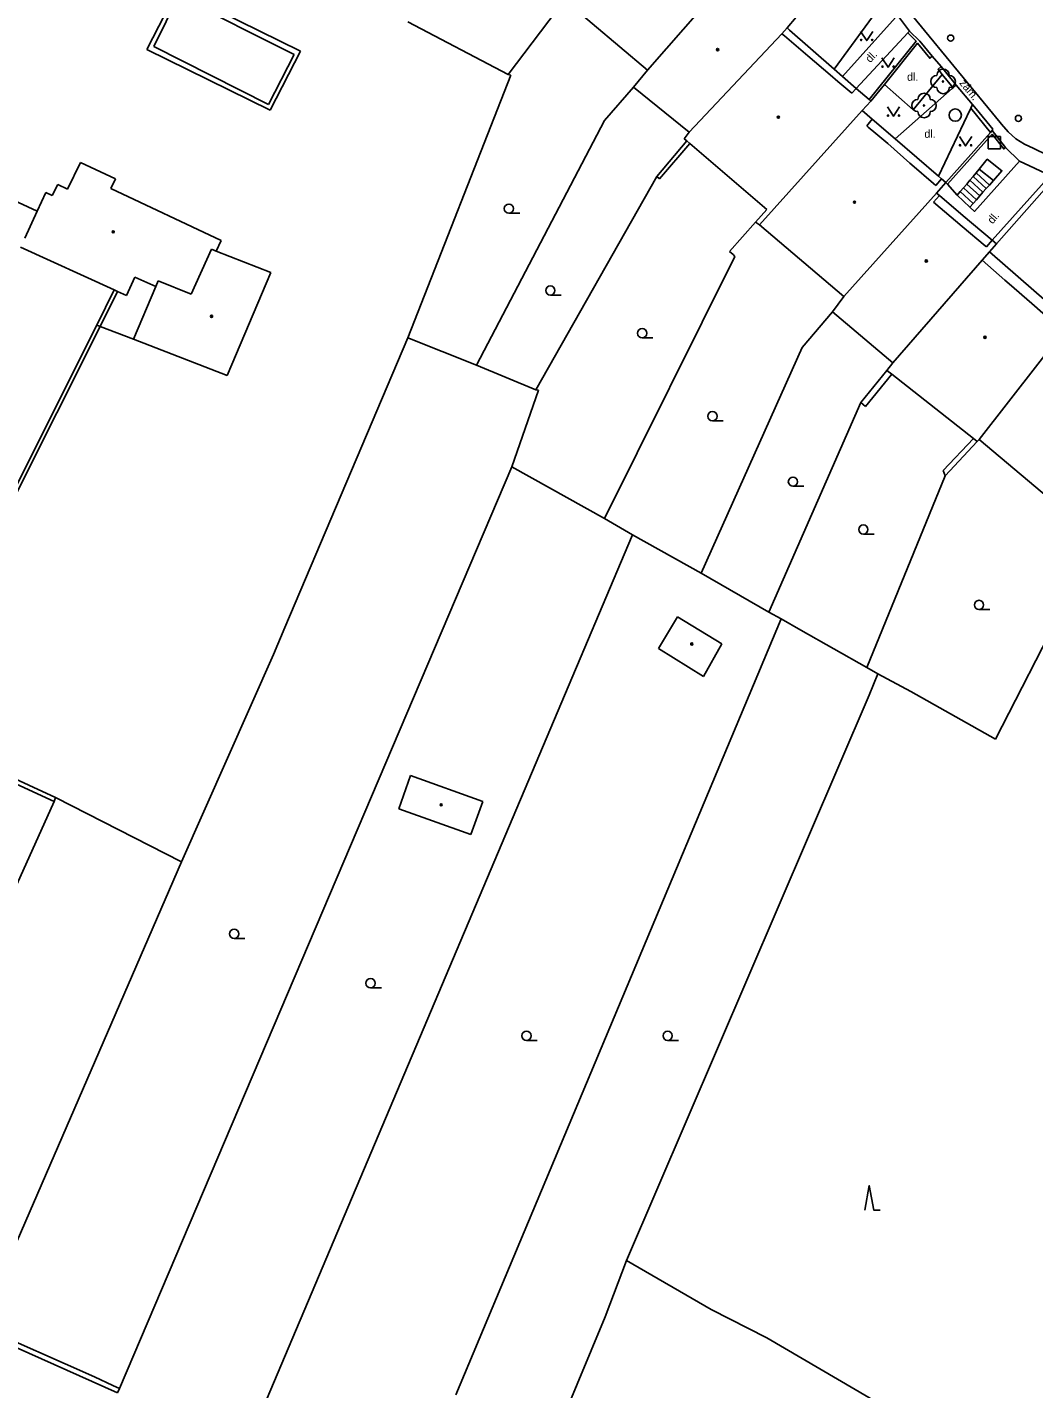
# Model space of a CAD drawing. Extents: x -600309 to -598967, y -1161267 to -1160292.
# Drawn here: x -600023.6 to -599941.8, y -1160821.7 to -1160711.1 of the extents above; entities that cross this region are included whole.
import ezdxf

# ---------------------------------------------------------------- set-up
doc = ezdxf.new("R2010")
doc.units = 0
for name, color, linetype in [('Level 10', 7, 'Continuous'), ('Level 11', 7, 'Continuous'), ('Level 22', 7, 'Continuous'), ('Level 26', 7, 'Continuous'), ('Level 27', 7, 'Continuous'), ('Level 28', 7, 'Continuous'), ('Level 36', 7, 'Continuous'), ('Level 39', 7, 'Continuous'), ('Level 40', 7, 'Continuous'), ('Level 5', 7, 'Continuous'), ('Level 51', 7, 'Continuous'), ('Level 52', 7, 'Continuous'), ('Level 54', 7, 'Continuous'), ('Level 8', 7, 'Continuous')]:
    doc.layers.add(name, color=color, linetype=linetype)

msp = doc.modelspace()

# ---------------------------------------------------------------- linework, layer by layer
at = {"layer": 'Level 10'}
for points in [[(-599972.15, -1160685.37), (-599963.56, -1160695.65), (-599958.13, -1160702.29), (-599951.34, -1160710.61), (-599944.5652, -1160718.8302), (-599944.45, -1160718.9699)], [(-599944.45, -1160718.9699), (-599943.9099, -1160719.6), (-599943.29, -1160720.15), (-599942.59, -1160720.6), (-599941.84, -1160720.95)], [(-599941.84, -1160720.95), (-599921.83, -1160730.68), (-599912.84, -1160735.04), (-599897.82, -1160742.4699), (-599882.1599, -1160750.1), (-599876.92, -1160738.9699), (-599874.96, -1160734.65), (-599883.28, -1160730.96), (-599891.87, -1160727.45), (-599900.5, -1160724)]]:
    msp.add_lwpolyline(points, dxfattribs=at)
at = {"layer": 'Level 11'}
for points in [[(-599958.05, -1160714.51), (-599954.12, -1160709.13)], [(-599953.07, -1160710.29), (-599957.38, -1160715.09)], [(-599952.9, -1160710.1), (-599951.92, -1160711.4099)], [(-599956.25, -1160716.08), (-599952.06, -1160711.56)], [(-599952.06, -1160711.56), (-599951.39, -1160712.2199), (-599955.21, -1160716.9699)], [(-599952.06, -1160711.56), (-599951.92, -1160711.4099)], [(-599951.92, -1160711.4099), (-599951.09, -1160712.23), (-599950.1, -1160713.45)], [(-599950.1, -1160713.45), (-599950.29, -1160713.61), (-599951.27, -1160712.4), (-599953.96, -1160715.75)], [(-599950.1, -1160713.45), (-599949.35, -1160714.29)], [(-599953.96, -1160715.75), (-599951.63, -1160717.79), (-599949.27, -1160714.93)], [(-599949.27, -1160714.93), (-599949.61, -1160714.5), (-599949.35, -1160714.29)], [(-599949.35, -1160714.29), (-599948.33, -1160715.55), (-599948.14, -1160715.79)], [(-599949.27, -1160714.93), (-599948.39, -1160716.01)], [(-599953.96, -1160715.75), (-599955.06, -1160717.1)], [(-599948.39, -1160716.01), (-599948.45, -1160716.06), (-599953.1, -1160720.1599)], [(-599948.14, -1160715.79), (-599948.39, -1160716.01)], [(-599948.14, -1160715.79), (-599946.81, -1160717.37)], [(-599949.57, -1160723.2), (-599947, -1160717.77), (-599946.95, -1160717.67)], [(-599946.95, -1160717.67), (-599946.81, -1160717.37)], [(-599946.95, -1160717.67), (-599945.34, -1160719.64)], [(-599946.81, -1160717.37), (-599946.52, -1160717.7199), (-599945.17, -1160719.37), (-599945.2, -1160719.48)], [(-599945.2, -1160719.48), (-599945.34, -1160719.64)], [(-599945.2, -1160719.48), (-599944.12, -1160720.85)], [(-599945.34, -1160719.64), (-599948.98, -1160723.71)], [(-599945.21, -1160719.79), (-599948.83, -1160723.84)], [(-599945.21, -1160719.79), (-599944.27, -1160720.98), (-599944.12, -1160720.85)], [(-599944.12, -1160720.85), (-599943, -1160721.9699)], [(-599947.02, -1160725.7), (-599946.64, -1160726.05), (-599943, -1160721.9699)], [(-599946.5, -1160722.9099), (-599946.26, -1160722.63)], [(-599946.26, -1160722.63), (-599945.61, -1160721.81), (-599944.42, -1160722.75), (-599945.11, -1160723.55)], [(-599945.11, -1160723.55), (-599946.26, -1160722.63)], [(-599943, -1160721.9699), (-599940.51, -1160723.14)], [(-599948.98, -1160723.71), (-599948.83, -1160723.84)], [(-599948.83, -1160723.84), (-599948.06, -1160724.74)], [(-599947.54, -1160724.13), (-599947.28, -1160723.83)], [(-599947.28, -1160723.83), (-599947.02, -1160723.52)], [(-599947.28, -1160723.83), (-599946.2199, -1160724.8)], [(-599947.02, -1160723.52), (-599946.76, -1160723.2199)], [(-599947.02, -1160723.52), (-599945.96, -1160724.5)], [(-599946.76, -1160723.2199), (-599946.5, -1160722.9099)], [(-599946.76, -1160723.2199), (-599945.69, -1160724.2)], [(-599946.5, -1160722.9099), (-599945.43, -1160723.9099)], [(-599945.43, -1160723.9099), (-599945.69, -1160724.2)], [(-599945.11, -1160723.55), (-599945.43, -1160723.9099)], [(-599945.2, -1160728.39), (-599940.51, -1160723.14)], [(-599940.14, -1160723.35), (-599944.87, -1160728.7)], [(-599948.06, -1160724.74), (-599947.8, -1160724.44)], [(-599948.06, -1160724.74), (-599947.02, -1160725.7)], [(-599947.8, -1160724.44), (-599947.54, -1160724.13)], [(-599947.8, -1160724.44), (-599946.76, -1160725.4)], [(-599947.54, -1160724.13), (-599946.49, -1160725.1)], [(-599946.2199, -1160724.8), (-599946.49, -1160725.1)], [(-599945.96, -1160724.5), (-599946.2199, -1160724.8)], [(-599945.69, -1160724.2), (-599945.96, -1160724.5)], [(-599946.76, -1160725.4), (-599947.02, -1160725.7)], [(-599946.49, -1160725.1), (-599946.76, -1160725.4)], [(-600016.13, -1160821.67), (-600016.29, -1160822.03)]]:
    msp.add_lwpolyline(points, dxfattribs=at)
at = {"layer": 'Level 22'}
for centre in [(-599949.2, -1160715.5), (-599950.75, -1160717.45)]:
    msp.add_circle(centre, 0.05, dxfattribs=at)
for centre, start, end in [((-599949.7, -1160715.5), 90, 270), ((-599949.2, -1160715), 0, 180), ((-599948.7, -1160715.5), 270, 90), ((-599949.2, -1160716), 180, 0), ((-599951.25, -1160717.45), 90, 270), ((-599950.75, -1160716.95), 0, 180), ((-599950.25, -1160717.45), 270, 90), ((-599950.75, -1160717.95), 180, 0)]:
    msp.add_arc(centre, 0.5, start, end, dxfattribs=at)
at = {"layer": 'Level 26'}
msp.add_lwpolyline([(-599945.54, -1160720.9699), (-599944.54, -1160720.9699), (-599944.54, -1160719.9699), (-599945.54, -1160719.9699)], close=True, dxfattribs=at)
at = {"layer": 'Level 27'}
msp.add_circle((-599948.21, -1160718.23), 0.5, dxfattribs=at)
at = {"layer": 'Level 28'}
for centre in [(-599948.58, -1160711.98), (-599943.08, -1160718.5)]:
    msp.add_circle(centre, 0.25, dxfattribs=at)
at = {"layer": 'Level 36'}
for p, q in [((-599984.48, -1160726.205), (-599983.605, -1160726.205)), ((-599981.11, -1160732.855), (-599980.235, -1160732.855)), ((-599973.65, -1160736.325), (-599972.775, -1160736.325)), ((-599967.94, -1160743.065), (-599967.065, -1160743.065)), ((-599961.4, -1160748.385), (-599960.525, -1160748.385)), ((-599955.68, -1160752.265), (-599954.805, -1160752.265)), ((-599946.28, -1160758.395), (-599945.405, -1160758.395)), ((-600006.8, -1160785.115), (-600005.925, -1160785.115)), ((-599995.7199, -1160789.125), (-599994.8449, -1160789.125)), ((-599983.05, -1160793.395), (-599982.175, -1160793.395)), ((-599971.58, -1160793.395), (-599970.705, -1160793.395))]:
    msp.add_line(p, q, dxfattribs=at)
for points in [[(-599955.9099, -1160711.43), (-599955.4099, -1160712.18), (-599954.9099, -1160711.43)], [(-599954.17, -1160713.59), (-599953.67, -1160714.34), (-599953.17, -1160713.59)], [(-599953.73, -1160717.57), (-599953.23, -1160718.32), (-599952.73, -1160717.57)], [(-599947.87, -1160719.98), (-599947.37, -1160720.73), (-599946.87, -1160719.98)], [(-599955.569, -1160807.1879), (-599955.194, -1160805.1879), (-599954.819, -1160807.1879), (-599954.319, -1160807.1879)]]:
    msp.add_lwpolyline(points, dxfattribs=at)
for centre, radius in [((-599955.8601, -1160712.1298), 0.05), ((-599954.9607, -1160712.1298), 0.05), ((-599954.1202, -1160714.2898), 0.05), ((-599953.2208, -1160714.2898), 0.05), ((-599953.6802, -1160718.2698), 0.05), ((-599952.7808, -1160718.2698), 0.05), ((-599947.8202, -1160720.6798), 0.05), ((-599946.9208, -1160720.6798), 0.05), ((-599984.4801, -1160725.8299), 0.375), ((-599981.1101, -1160732.4799), 0.375), ((-599973.6501, -1160735.9499), 0.375), ((-599967.9401, -1160742.6899), 0.375), ((-599961.4001, -1160748.0099), 0.375), ((-599955.6801, -1160751.8899), 0.375), ((-599946.2801, -1160758.0199), 0.375), ((-600006.8001, -1160784.7399), 0.375), ((-599995.72, -1160788.7499), 0.375), ((-599983.0501, -1160793.0199), 0.375), ((-599971.5801, -1160793.0199), 0.375)]:
    msp.add_circle(centre, radius, dxfattribs=at)
at = {"layer": 'Level 39'}
for centre, radius in [((-599967.52, -1160712.9099), 0.09), ((-599967.52, -1160712.9099), 0.0398), ((-599962.58, -1160718.4), 0.09), ((-599962.58, -1160718.4), 0.0398), ((-599956.4, -1160725.3), 0.09), ((-599956.4, -1160725.3), 0.0398), ((-600016.63, -1160727.71), 0.09), ((-600016.63, -1160727.71), 0.0398), ((-599950.57, -1160730.08), 0.09), ((-599950.57, -1160730.08), 0.0398), ((-600008.64, -1160734.57), 0.09), ((-600008.64, -1160734.57), 0.0398), ((-599945.8, -1160736.28), 0.09), ((-599945.8, -1160736.28), 0.0398), ((-599969.62, -1160761.19), 0.09), ((-599969.62, -1160761.19), 0.0398), ((-599989.98, -1160774.26), 0.09), ((-599989.98, -1160774.26), 0.0398)]:
    msp.add_circle(centre, radius, dxfattribs=at)
at = {"layer": 'Level 5'}
for points in [[(-599973.21, -1160714.58), (-599965.87, -1160706.18)], [(-599973.21, -1160714.58), (-599979.96, -1160708.86)], [(-599961.14, -1160710.27), (-599961.88, -1160711.15)], [(-599969.83, -1160719.63), (-599962.29, -1160711.63)], [(-599961.88, -1160711.15), (-599962.29, -1160711.63)], [(-599962.29, -1160711.63), (-599962.09, -1160711.8)], [(-599961.88, -1160711.15), (-599961.69, -1160711.32)], [(-599961.69, -1160711.32), (-599958.05, -1160714.51)], [(-599962.09, -1160711.8), (-599960.38, -1160713.25)], [(-599960.38, -1160713.25), (-599960.19, -1160713.4099)], [(-599960.19, -1160713.4099), (-599958.38, -1160714.96)], [(-599973.21, -1160714.58), (-599974.35, -1160715.96)], [(-599958.38, -1160714.96), (-599957.75, -1160715.5)], [(-599958.05, -1160714.51), (-599957.38, -1160715.09)], [(-599957.38, -1160715.09), (-599956.25, -1160716.08)], [(-599969.83, -1160719.63), (-599974.35, -1160715.96)], [(-599957.75, -1160715.5), (-599956.61, -1160716.45)], [(-599956.61, -1160716.45), (-599956.25, -1160716.08)], [(-599956.25, -1160716.08), (-599955.21, -1160716.9699)], [(-599955.06, -1160717.1), (-599955.77, -1160717.85)], [(-599955.21, -1160716.9699), (-599955.06, -1160717.1)], [(-599964.13, -1160727.14), (-599955.77, -1160717.85)], [(-599955.77, -1160717.85), (-599954.95, -1160718.57)], [(-599954.95, -1160718.57), (-599955.4, -1160719.1)], [(-599955.4, -1160719.1), (-599955.28, -1160719.2)], [(-599955.28, -1160719.2), (-599954.6599, -1160719.73)], [(-599954.95, -1160718.57), (-599953.1, -1160720.1599)], [(-599969.83, -1160719.63), (-599970.24, -1160720.15)], [(-599970.24, -1160720.15), (-599970.02, -1160720.33)], [(-599969.77, -1160720.53), (-599970.02, -1160720.33)], [(-599963.51, -1160725.89), (-599969.77, -1160720.53)], [(-599954.6599, -1160719.73), (-599953.69, -1160720.55)], [(-599953.69, -1160720.55), (-599951.89, -1160722.13)], [(-599953.1, -1160720.1599), (-599949.57, -1160723.2)], [(-600019.29, -1160722.09), (-600020.35, -1160724.25)], [(-600016.45, -1160723.4099), (-600019.29, -1160722.09)], [(-599951.89, -1160722.13), (-599951.74, -1160722.26)], [(-599951.74, -1160722.26), (-599949.99, -1160723.8)], [(-600021.14, -1160723.86), (-600021.58, -1160724.77)], [(-600020.35, -1160724.25), (-600021.14, -1160723.86)], [(-600016.82, -1160724.2), (-600016.45, -1160723.4099)], [(-599949.99, -1160723.8), (-599949.8, -1160723.96)], [(-599949.8, -1160723.96), (-599949.32, -1160723.42)], [(-599948.98, -1160723.71), (-599949.73, -1160724.58)], [(-599949.57, -1160723.2), (-599949.32, -1160723.42)], [(-599949.32, -1160723.42), (-599948.98, -1160723.71)], [(-600022.11, -1160724.52), (-600022.81, -1160726.03)], [(-600021.58, -1160724.77), (-600022.11, -1160724.52)], [(-600007.87, -1160728.42), (-600016.82, -1160724.2)], [(-599957.26, -1160732.96), (-599949.73, -1160724.58)], [(-599949.5, -1160724.77), (-599949.9699, -1160725.3)], [(-599949.73, -1160724.58), (-599949.5, -1160724.77)], [(-599949.5, -1160724.77), (-599947.57, -1160726.4)], [(-600022.81, -1160726.03), (-600023.82, -1160728.23)], [(-599964.43, -1160726.94), (-599963.51, -1160725.89)], [(-599949.9699, -1160725.3), (-599947.64, -1160727.27)], [(-599964.13, -1160727.14), (-599964.43, -1160726.94)], [(-599957.26, -1160732.96), (-599964.13, -1160727.14)], [(-599947.64, -1160727.27), (-599945.78, -1160728.84)], [(-599947.57, -1160726.4), (-599945.2, -1160728.39)], [(-600024.1599, -1160728.9699), (-600016.54, -1160732.43)], [(-600008.65, -1160729.12), (-600010.31, -1160732.78)], [(-600008.27, -1160729.27), (-600008.65, -1160729.12)], [(-600008.27, -1160729.27), (-600007.87, -1160728.42)], [(-600003.82, -1160731.02), (-600008.27, -1160729.27)], [(-599945.44, -1160729.35), (-599946.03, -1160730.02)], [(-599945.78, -1160728.84), (-599945.6599, -1160728.94)], [(-599945.6599, -1160728.94), (-599945.2, -1160728.39)], [(-599944.87, -1160728.7), (-599945.44, -1160729.35)], [(-599945.44, -1160729.35), (-599940.78, -1160733.4099)], [(-599945.2, -1160728.39), (-599944.87, -1160728.7)], [(-599953.29, -1160738.35), (-599946.03, -1160730.02)], [(-599946.03, -1160730.02), (-599944.18, -1160731.64)], [(-600015.55, -1160732.88), (-600014.88, -1160731.39)], [(-600014.88, -1160731.39), (-600013.18, -1160732.1599)], [(-600012.99, -1160731.7), (-600013.18, -1160732.1599)], [(-600010.31, -1160732.78), (-600012.99, -1160731.7)], [(-600007.36, -1160739.39), (-600003.82, -1160731.02)], [(-599944.18, -1160731.64), (-599943.84, -1160731.93)], [(-600016.54, -1160732.43), (-600016.28, -1160732.55)], [(-600016.28, -1160732.55), (-600015.55, -1160732.88)], [(-600013.18, -1160732.1599), (-600014.9699, -1160736.43)], [(-599943.84, -1160731.93), (-599941.99, -1160733.54)], [(-599957.26, -1160732.96), (-599958.19, -1160734.2199)], [(-599941.99, -1160733.54), (-599940.42, -1160734.9099)], [(-599953.29, -1160738.35), (-599958.19, -1160734.2199)], [(-599946.27, -1160744.57), (-599939.12, -1160735.39)], [(-600014.9699, -1160736.43), (-600007.36, -1160739.39)], [(-599953.29, -1160738.35), (-599953.78, -1160738.9699)], [(-599953.37, -1160739.28), (-599953.78, -1160738.9699)], [(-599946.74, -1160744.5), (-599953.37, -1160739.28)], [(-599946.43, -1160744.75), (-599946.74, -1160744.5)], [(-599946.43, -1160744.75), (-599946.27, -1160744.57)], [(-599939.45, -1160750.31), (-599946.27, -1160744.57)]]:
    msp.add_lwpolyline(points, dxfattribs=at)
at = {"layer": 'Level 51'}
for points in [[(-599979.96, -1160708.86), (-599984.55, -1160714.92)], [(-599984.55, -1160714.92), (-599992.69, -1160710.65)], [(-599984.33, -1160714.98), (-599992.68, -1160736.33)], [(-599984.55, -1160714.92), (-599984.33, -1160714.98)], [(-599976.7, -1160718.68), (-599974.35, -1160715.96)], [(-599987.12, -1160738.54), (-599976.7, -1160718.68)], [(-599970.02, -1160720.33), (-599972.4699, -1160723.23)], [(-600033.52, -1160721.09), (-600022.81, -1160726.03)], [(-599972.4699, -1160723.23), (-599982.3, -1160740.54)], [(-599964.43, -1160726.94), (-599966.55, -1160729.32)], [(-599966.55, -1160729.32), (-599966.26, -1160729.56)], [(-599966.11, -1160729.73), (-599976.7199, -1160751)], [(-599966.26, -1160729.56), (-599966.11, -1160729.73)], [(-600016.54, -1160732.43), (-600017.9699, -1160735.29)], [(-599958.19, -1160734.2199), (-599960.6599, -1160737.12)], [(-600017.9699, -1160735.29), (-600017.69, -1160735.39)], [(-600014.9699, -1160736.43), (-600017.69, -1160735.39)], [(-599992.68, -1160736.33), (-600002.69, -1160759.86)], [(-599987.12, -1160738.54), (-599992.68, -1160736.33)], [(-599960.6599, -1160737.12), (-599968.85, -1160755.44)], [(-599982.3, -1160740.54), (-599987.12, -1160738.54)], [(-599953.78, -1160738.9699), (-599955.89, -1160741.58)], [(-599982.07, -1160740.58), (-599982.3, -1160740.54)], [(-599984.24, -1160746.81), (-599982.07, -1160740.58)], [(-599955.89, -1160741.58), (-599963.37, -1160758.62)], [(-599949.03, -1160747.53), (-599946.43, -1160744.75)], [(-599984.24, -1160746.81), (-600016.13, -1160821.67)], [(-599976.7199, -1160751), (-599984.24, -1160746.81)], [(-599955.4, -1160763.1), (-599949.03, -1160747.53)], [(-599974.43, -1160752.32), (-599976.7199, -1160751)], [(-599974.43, -1160752.32), (-600006, -1160826.86), (-600006.58, -1160828.23)], [(-599968.85, -1160755.44), (-599974.43, -1160752.32)], [(-599963.37, -1160758.62), (-599968.85, -1160755.44)], [(-599962.37, -1160759.15), (-599988.79, -1160822.19)], [(-599962.37, -1160759.15), (-599963.37, -1160758.62)], [(-599960.75, -1160760.07), (-599962.37, -1160759.15)], [(-599944.95, -1160768.92), (-599939.51, -1160758.3)], [(-600002.69, -1160759.86), (-600003.61, -1160762.04)], [(-599955.4, -1160763.1), (-599960.75, -1160760.07)], [(-600021.44, -1160773.99), (-600050.44, -1160760.64)], [(-600003.61, -1160762.04), (-600011.07, -1160778.88)], [(-599954.49, -1160763.63), (-599955.4, -1160763.1)], [(-599954.49, -1160763.63), (-599955.2199, -1160765.34)], [(-599951.82, -1160765.06), (-599954.49, -1160763.63)], [(-599955.2199, -1160765.34), (-599974.93, -1160811.26)], [(-599951.82, -1160765.06), (-599944.95, -1160768.92)], [(-600021.33, -1160773.67), (-600021.44, -1160773.99)], [(-600011.07, -1160778.88), (-600021.33, -1160773.67)], [(-600021.44, -1160773.99), (-600024.95, -1160781.81)], [(-600011.07, -1160778.88), (-600027.47, -1160816.6), (-600027.63, -1160816.97)], [(-599976.65, -1160815.85), (-599974.93, -1160811.26)], [(-599968.05, -1160815.26), (-599974.93, -1160811.26)], [(-599963.51, -1160817.55), (-599968.05, -1160815.26)], [(-600018.1599, -1160820.73), (-600027.47, -1160816.6)], [(-599976.65, -1160815.85), (-599981.21, -1160826.79)], [(-599949.5, -1160825.75), (-599963.51, -1160817.55)], [(-600016.65, -1160821.43), (-600018.1599, -1160820.73)], [(-600016.13, -1160821.67), (-600016.65, -1160821.43)]]:
    msp.add_lwpolyline(points, dxfattribs=at)
at = {"layer": 'Level 52'}
for points in [[(-599972.32, -1160761.56), (-599970.79, -1160758.98)], [(-599970.79, -1160758.98), (-599967.18, -1160761.17)], [(-599968.6599, -1160763.84), (-599972.32, -1160761.56)], [(-599967.18, -1160761.17), (-599968.6599, -1160763.84)], [(-599993.43, -1160774.58), (-599992.4699, -1160771.87)], [(-599992.4699, -1160771.87), (-599986.59, -1160773.98)], [(-599987.57, -1160776.68), (-599993.43, -1160774.58)], [(-599986.59, -1160773.98), (-599987.57, -1160776.68)]]:
    msp.add_lwpolyline(points, dxfattribs=at)
at = {"layer": 'Level 54'}
for points in [[(-600013.89, -1160712.9099), (-600011.43, -1160708.07)], [(-600011.43, -1160708.07), (-600001.4099, -1160713.05)], [(-600013.33, -1160712.6599), (-600011.32, -1160708.58)], [(-600011.32, -1160708.58), (-600001.93, -1160713.3)], [(-600004.02, -1160717.38), (-600013.33, -1160712.6599)], [(-600003.87, -1160717.84), (-600013.89, -1160712.9099)], [(-600001.93, -1160713.3), (-600004.02, -1160717.38)], [(-600001.4099, -1160713.05), (-600003.87, -1160717.84)], [(-599969.77, -1160720.53), (-599972.25, -1160723.4)], [(-599972.25, -1160723.4), (-599972.4699, -1160723.23)], [(-600017.69, -1160735.39), (-600016.28, -1160732.55)], [(-600017.9699, -1160735.29), (-600025, -1160749.34)], [(-600024.73, -1160749.44), (-600017.69, -1160735.39)], [(-599953.37, -1160739.28), (-599955.5, -1160741.89)], [(-599955.5, -1160741.89), (-599955.89, -1160741.58)], [(-599946.74, -1160744.5), (-599949.2, -1160747.11)], [(-599949.2, -1160747.11), (-599949.03, -1160747.53)], [(-600050.27, -1160760.28), (-600021.33, -1160773.67)], [(-600027.63, -1160816.97), (-600016.29, -1160822.03)]]:
    msp.add_lwpolyline(points, dxfattribs=at)
at = {"layer": 'Level 8'}
for points in [[(-599962.09, -1160711.8), (-599960.38, -1160713.25)], [(-599960.19, -1160713.4099), (-599958.38, -1160714.96)], [(-599951.89, -1160722.13), (-599953.69, -1160720.55)], [(-599949.99, -1160723.8), (-599951.74, -1160722.26)], [(-599947.64, -1160727.27), (-599945.78, -1160728.84)], [(-599946.03, -1160730.02), (-599944.18, -1160731.64)], [(-599943.84, -1160731.93), (-599941.99, -1160733.54)]]:
    msp.add_lwpolyline(points, dxfattribs=at)

# ---------------------------------------------------------------- texts
at = {"layer": 'Level 40'}
for s, rotation, p in [('dl.', 47.09, (-599955.12, -1160714.02)), ('zám.', 309.48, (-599947.92, -1160715.64)), ('dl.', 49.81, (-599945.18, -1160727.12))]:
    msp.add_text(s, height=0.65, rotation=rotation, dxfattribs=at).set_placement(p)
for p in [(-599952.13, -1160715.44), (-599950.7199, -1160720.07)]:
    msp.add_text('dl.', height=0.65, dxfattribs=at).set_placement(p)

doc.saveas('drawing.dxf')
